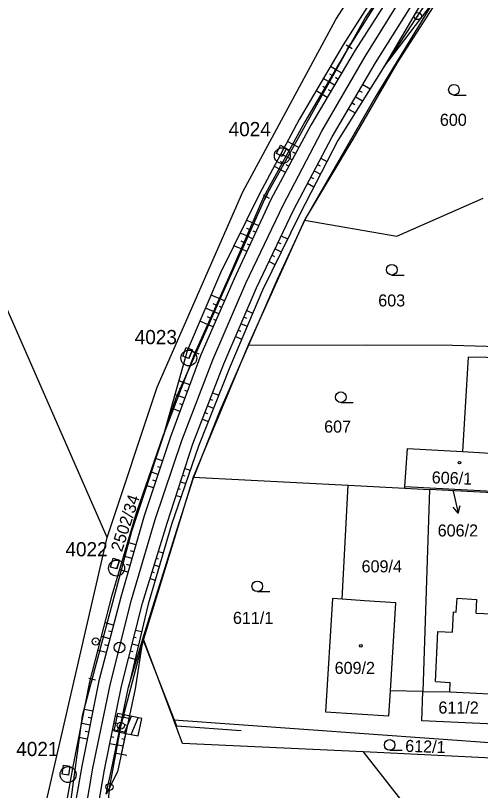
# Model space of a CAD drawing. Extents: x -558358 to -557517, y -1073786 to -1073189.
# Drawn here: x -558299.7 to -558234.1, y -1073668.8 to -1073559.5 of the extents above; entities that cross this region are included whole.
import ezdxf

# ---------------------------------------------------------------- set-up
doc = ezdxf.new("R2010")
doc.units = 0
for name, color, linetype in [('Body', 7, 'Continuous'), ('Hranice parcel', 7, 'Continuous'), ('Kolej', 7, 'Continuous'), ('Lomové body_krizky', 7, 'Continuous'), ('Návěst místo trati', 7, 'Continuous'), ('Parcelní čísla', 7, 'Continuous'), ('Plot - zábradlí', 7, 'Continuous'), ('Pop  PČ popisy', 7, 'Continuous'), ('Přejezd - štěrkové lože', 7, 'Continuous'), ('Sonda - šrafa - vrstevnice', 7, 'Continuous'), ('Svazek obcí údolí Desné', 7, 'Continuous'), ('Vnitřní kresba', 7, 'Continuous'), ('Vrstva 1', 7, 'Continuous'), ('Vrstva 60', 7, 'Continuous'), ('Značky budov', 7, 'Continuous'), ('Značky kultur', 7, 'Continuous'), ('ŽKN drážní hranice', 7, 'Continuous')]:
    doc.layers.add(name, color=color, linetype=linetype)

msp = doc.modelspace()

# ---------------------------------------------------------------- linework, layer by layer
at = {"layer": 'Body'}
for p, q in [((-558262.32, -1073577.78), (-558261.49, -1073578.24)), ((-558262.1, -1073579.36), (-558262.92, -1073578.93)), ((-558275.63, -1073606.33), (-558274.76, -1073606.67)), ((-558275.24, -1073607.87), (-558276.1, -1073607.53)), ((-558285.94, -1073636.03), (-558285.03, -1073636.3)), ((-558285.39, -1073637.54), (-558286.32, -1073637.3)), ((-558292.94, -1073665.22), (-558292.02, -1073665.39)), ((-558292.22, -1073666.67), (-558293.14, -1073666.49))]:
    msp.add_line(p, q, dxfattribs=at)
for points in [[(-558261.49, -1073578.24), (-558262.1, -1073579.36), (-558262.92, -1073578.93), (-558262.32, -1073577.78), (-558261.49, -1073578.24)], [(-558262.92, -1073578.93), (-558262.92, -1073578.93), (-558262.32, -1073577.78), (-558262.32, -1073577.78)], [(-558274.76, -1073606.67), (-558275.24, -1073607.87), (-558276.1, -1073607.53), (-558275.63, -1073606.33), (-558274.76, -1073606.67)], [(-558276.1, -1073607.53), (-558276.1, -1073607.53), (-558275.63, -1073606.33), (-558275.63, -1073606.33)], [(-558275.24, -1073607.87), (-558275.24, -1073607.87), (-558274.76, -1073606.67), (-558274.76, -1073606.67)], [(-558285.03, -1073636.3), (-558285.39, -1073637.54), (-558286.32, -1073637.3), (-558285.94, -1073636.03), (-558285.03, -1073636.3)], [(-558286.32, -1073637.3), (-558286.32, -1073637.3), (-558285.94, -1073636.03), (-558285.94, -1073636.03)], [(-558285.39, -1073637.54), (-558285.39, -1073637.54), (-558285.03, -1073636.3)], [(-558292.02, -1073665.39), (-558292.22, -1073666.67), (-558293.14, -1073666.49), (-558292.94, -1073665.22), (-558292.02, -1073665.39)], [(-558293.14, -1073666.49), (-558293.14, -1073666.49), (-558292.94, -1073665.22), (-558292.94, -1073665.22)]]:
    msp.add_lwpolyline(points, dxfattribs=at)
at = {"layer": 'Hranice parcel'}
for p, q in [((-558286.79, -1073633.11), (-558314.35, -1073570.26)), ((-558274.67, -1073624.61), (-558252.77, -1073625.76)), ((-558253.62, -1073641.82), (-558252.77, -1073625.76)), ((-558252.77, -1073625.76), (-558244.78, -1073626.18)), ((-558244.78, -1073626.18), (-558244.8, -1073625.91)), ((-558244.8, -1073625.91), (-558230.66, -1073626.67)), ((-558244.78, -1073626.18), (-558241.33, -1073626.36)), ((-558241.33, -1073626.36), (-558242.25, -1073654.84)), ((-558230.7, -1073626.92), (-558241.33, -1073626.36)), ((-558277.36, -1073658.89), (-558281.64, -1073647.46)), ((-558242.25, -1073654.84), (-558246.82, -1073654.76)), ((-558214.98, -1073663.38), (-558277.36, -1073658.89)), ((-558235.56, -1073682.51), (-558250.61, -1073663.38)), ((-558196.23, -1073665.95), (-558250.61, -1073663.38))]:
    msp.add_line(p, q, dxfattribs=at)
for points in [[(-558258.93, -1073588.36), (-558245.95, -1073590.61), (-558233.77, -1073585.24)], [(-558266.9, -1073605.97), (-558250.26, -1073605.94), (-558238.1, -1073605.99), (-558233.28, -1073606.15), (-558214.77, -1073606.72), (-558208.24, -1073606.85)], [(-558201.17, -1073622.6), (-558216.08, -1073622.11), (-558216.01, -1073620.62), (-558215.37, -1073608.44), (-558225.51, -1073607.88), (-558235.86, -1073607.68), (-558236.68, -1073621.01)], [(-558244.8, -1073625.91), (-558244.42, -1073620.56), (-558236.68, -1073621.01)], [(-558236.68, -1073621.01), (-558230.37, -1073621.38), (-558230.66, -1073626.67)], [(-558253.62, -1073641.82), (-558255.01, -1073641.72), (-558256, -1073657.72), (-558247.04, -1073658.27), (-558246.82, -1073654.76)], [(-558246.82, -1073654.76), (-558246.07, -1073642.32), (-558250.48, -1073642.05), (-558253.62, -1073641.82)], [(-558214.83, -1073660.26), (-558242.39, -1073658.97), (-558242.25, -1073654.84)], [(-558242.25, -1073654.84), (-558238.47, -1073654.91), (-558229.12, -1073655.37), (-558229.2, -1073656.96), (-558221.9, -1073657.32), (-558221.78, -1073654.92), (-558214.58, -1073655.27)], [(-558250.61, -1073663.38), (-558276.13, -1073662.17), (-558277.36, -1073658.89)]]:
    msp.add_lwpolyline(points, dxfattribs=at)
at = {"layer": 'Kolej'}
msp.add_lwpolyline([(-558287.37, -1073784.16), (-558289.56, -1073772.87), (-558290.66, -1073766.21), (-558291.24, -1073762.21), (-558292.77, -1073749.06), (-558293.62, -1073737.47), (-558294.02, -1073725.05), (-558293.93, -1073713.18), (-558293.34, -1073701.02), (-558292.27, -1073689.01), (-558290.77, -1073677.31), (-558288.8, -1073665.65), (-558286.32, -1073653.74), (-558283.34, -1073641.94), (-558280, -1073630.57), (-558276.23, -1073619.43), (-558271.87, -1073608.04), (-558267.23, -1073597.24), (-558261.98, -1073586.24), (-558256.49, -1073575.8), (-558250.41, -1073565.28), (-558246.06, -1073558.3)], dxfattribs=at)
at = {"layer": 'Lomové body_krizky'}
msp.add_line((-558247.8, -1073566.83), (-558237.59, -1073553.32), dxfattribs=at)
for points in [[(-558243.55, -1073526.52), (-558241.09, -1073532.31), (-558239.34, -1073536.46), (-558240.77, -1073539.1), (-558240.78, -1073543.51), (-558244.12, -1073548.8), (-558253.49, -1073563.6), (-558259.69, -1073574.14), (-558265.34, -1073584.72), (-558270.8, -1073595.81), (-558275.48, -1073606.81), (-558278.77, -1073618.5)], [(-558238.82, -1073534.05), (-558238.07, -1073536.86), (-558239.2, -1073538.21), (-558240, -1073543.71), (-558243.46, -1073549.18), (-558252.76, -1073564.02), (-558258.92, -1073574.47), (-558264.72, -1073585.09), (-558269.64, -1073596.42), (-558274.5, -1073607.3), (-558278.77, -1073618.5)], [(-558233.31, -1073548.35), (-558233.96, -1073547.13), (-558235.35, -1073547.54), (-558238.57, -1073552.68), (-558247.8, -1073566.83)], [(-558281.76, -1073647.44), (-558282.83, -1073654.48), (-558285.33, -1073666.2), (-558286.94, -1073669.34)], [(-558286.94, -1073669.34), (-558286.22, -1073666.1), (-558283.78, -1073654.25), (-558281.76, -1073647.44)]]:
    msp.add_lwpolyline(points, dxfattribs=at)
at = {"layer": 'Návěst místo trati'}
for p, q in [((-558243.02, -1073559.57), (-558242.92, -1073559.57)), ((-558243.02, -1073559.57), (-558242.92, -1073559.57)), ((-558253.08, -1073563.61), (-558252.23, -1073564.13)), ((-558252.91, -1073564.3), (-558252.4, -1073563.44)), ((-558264.8, -1073584.8), (-558263.91, -1073585.25)), ((-558264.58, -1073585.47), (-558264.13, -1073584.58)), ((-558274.76, -1073606.83), (-558273.84, -1073607.21)), ((-558274.49, -1073607.48), (-558274.11, -1073606.56)), ((-558288.45, -1073647.79), (-558288.35, -1073647.79)), ((-558288.45, -1073647.79), (-558288.35, -1073647.79)), ((-558288.78, -1073652.65), (-558289.01, -1073653.62)), ((-558288.41, -1073653.24), (-558289.38, -1073653.02)), ((-558285.36, -1073660.51), (-558284.35, -1073658.16)), ((-558283.38, -1073658.36), (-558284.38, -1073660.71)), ((-558283.4, -1073660.92), (-558282.4, -1073658.57)), ((-558285.48, -1073663.54), (-558284.01, -1073663.85))]:
    msp.add_line(p, q, dxfattribs=at)
msp.add_lwpolyline([(-558284.74, -1073663.7), (-558284.13, -1073660.76), (-558282.42, -1073661.12), (-558281.91, -1073658.67), (-558285.33, -1073657.96), (-558285.84, -1073660.4), (-558284.13, -1073660.76)], dxfattribs=at)
for centre, radius in [((-558242.97, -1073559.57), 0.5), ((-558242.97, -1073559.57), 0.5), ((-558288.4, -1073647.79), 0.5), ((-558288.4, -1073647.79), 0.5), ((-558285.03, -1073648.64), 0.75)]:
    msp.add_circle(centre, radius, dxfattribs=at)
at = {"layer": 'Plot - zábradlí'}
msp.add_lwpolyline([(-558267.89, -1073660.39), (-558276.96, -1073659.75), (-558281.76, -1073647.44), (-558277.17, -1073632.83), (-558274.66, -1073624.85), (-558270.86, -1073615.23), (-558262.75, -1073596.69), (-558258.8, -1073588.16), (-558252.1, -1073576.95), (-558245.86, -1073566.23), (-558237.59, -1073553.32), (-558234.22, -1073548.55), (-558231.78, -1073553.91)], dxfattribs=at)
at = {"layer": 'Pop  PČ popisy'}
for p, q in [((-558238.03, -1073626.44), (-558237.95, -1073626.78)), ((-558237.95, -1073626.78), (-558237.28, -1073629.7)), ((-558237.28, -1073629.7), (-558237.01, -1073628.62)), ((-558237.28, -1073629.7), (-558237.99, -1073628.84))]:
    msp.add_line(p, q, dxfattribs=at)
at = {"layer": 'Přejezd - štěrkové lože'}
for p, q in [((-558253.72, -1073567.59), (-558254.57, -1073567.09)), ((-558254.23, -1073568.45), (-558254.57, -1073568.25)), ((-558254.73, -1073569.31), (-558255.58, -1073568.81)), ((-558250.72, -1073569.23), (-558249.68, -1073569.83)), ((-558255.75, -1073571.03), (-558256.6, -1073570.53)), ((-558255.24, -1073570.18), (-558255.58, -1073569.97)), ((-558251.22, -1073570.09), (-558250.82, -1073570.32)), ((-558252.23, -1073571.81), (-558251.85, -1073572.04)), ((-558251.73, -1073570.95), (-558250.75, -1073571.53)), ((-558252.74, -1073572.68), (-558251.81, -1073573.22)), ((-558259.75, -1073578.09), (-558260.64, -1073577.62)), ((-558260.7, -1073579.86), (-558261.6, -1073579.37)), ((-558260.23, -1073578.97), (-558260.58, -1073578.78)), ((-558261.17, -1073580.74), (-558261.53, -1073580.54)), ((-558257.11, -1073580.51), (-558256.76, -1073580.7)), ((-558256.64, -1073579.63), (-558255.78, -1073580.08)), ((-558261.64, -1073581.62), (-558262.56, -1073581.13)), ((-558257.58, -1073581.4), (-558256.7, -1073581.86)), ((-558258.04, -1073582.28), (-558257.69, -1073582.47)), ((-558258.51, -1073583.16), (-558257.62, -1073583.64)), ((-558265.41, -1073589.15), (-558266.31, -1073588.74)), ((-558265.83, -1073590.06), (-558266.18, -1073589.9)), ((-558266.26, -1073590.97), (-558267.1, -1073590.57)), ((-558262.66, -1073591.49), (-558262.31, -1073591.66)), ((-558262.23, -1073590.59), (-558261.34, -1073591.01)), ((-558267.1, -1073592.78), (-558267.9, -1073592.41)), ((-558266.68, -1073591.87), (-558267.01, -1073591.72)), ((-558263.09, -1073592.4), (-558262.22, -1073592.81)), ((-558263.52, -1073593.3), (-558263.18, -1073593.46)), ((-558263.95, -1073594.21), (-558263.11, -1073594.6)), ((-558270.25, -1073599.75), (-558270.98, -1073599.43)), ((-558271.04, -1073601.58), (-558271.8, -1073601.26)), ((-558270.65, -1073600.67), (-558270.94, -1073600.54)), ((-558267.08, -1073601.12), (-558266.26, -1073601.47)), ((-558271.44, -1073602.5), (-558271.75, -1073602.37)), ((-558267.48, -1073602.04), (-558267.14, -1073602.18)), ((-558271.84, -1073603.42), (-558272.62, -1073603.08)), ((-558267.87, -1073602.96), (-558267.03, -1073603.32)), ((-558268.27, -1073603.87), (-558267.93, -1073604.02)), ((-558268.66, -1073604.79), (-558267.81, -1073605.16)), ((-558275.12, -1073611.58), (-558276.01, -1073611.26)), ((-558275.82, -1073613.46), (-558276.72, -1073613.12)), ((-558275.47, -1073612.52), (-558275.83, -1073612.39)), ((-558271.9, -1073612.7), (-558271.03, -1073613.04)), ((-558276.16, -1073614.4), (-558276.53, -1073614.26)), ((-558272.26, -1073613.63), (-558271.92, -1073613.77)), ((-558276.51, -1073615.33), (-558277.43, -1073614.99)), ((-558272.99, -1073615.5), (-558272.65, -1073615.63)), ((-558272.63, -1073614.57), (-558271.77, -1073614.9)), ((-558273.35, -1073616.43), (-558272.5, -1073616.76)), ((-558278.98, -1073622.32), (-558279.97, -1073621.99)), ((-558279.29, -1073623.27), (-558279.69, -1073623.14)), ((-558279.61, -1073624.22), (-558280.62, -1073623.88)), ((-558276.13, -1073624.32), (-558275.83, -1073624.42)), ((-558275.82, -1073623.37), (-558275.05, -1073623.62)), ((-558279.93, -1073625.17), (-558280.33, -1073625.03)), ((-558276.44, -1073625.28), (-558275.7, -1073625.51)), ((-558280.24, -1073626.12), (-558281.28, -1073625.77)), ((-558276.74, -1073626.23), (-558276.46, -1073626.32)), ((-558277.05, -1073627.18), (-558276.35, -1073627.4)), ((-558282.74, -1073634.18), (-558283.87, -1073633.85)), ((-558283.02, -1073635.14), (-558283.47, -1073635.01)), ((-558279.54, -1073635.08), (-558278.88, -1073635.29)), ((-558283.3, -1073636.1), (-558284.44, -1073635.77)), ((-558279.84, -1073636.04), (-558279.57, -1073636.12)), ((-558283.57, -1073637.06), (-558284.03, -1073636.93)), ((-558280.13, -1073637), (-558279.44, -1073637.21)), ((-558283.85, -1073638.02), (-558285.01, -1073637.69)), ((-558280.43, -1073637.95), (-558280.15, -1073638.04)), ((-558280.72, -1073638.91), (-558280.01, -1073639.13)), ((-558285.89, -1073645.48), (-558287.07, -1073645.18)), ((-558282.76, -1073646.19), (-558281.92, -1073646.4)), ((-558286.39, -1073647.42), (-558287.57, -1073647.11)), ((-558286.14, -1073646.45), (-558286.61, -1073646.33)), ((-558283.01, -1073647.16), (-558282.67, -1073647.25)), ((-558286.64, -1073648.39), (-558287.11, -1073648.26)), ((-558283.25, -1073648.13), (-558282.38, -1073648.35)), ((-558286.89, -1073649.35), (-558288.06, -1073649.05)), ((-558283.5, -1073649.1), (-558283.14, -1073649.19)), ((-558283.74, -1073650.07), (-558282.84, -1073650.3)), ((-558288.8, -1073657.64), (-558289.98, -1073657.4)), ((-558285.61, -1073658.27), (-558284.65, -1073658.46)), ((-558289.19, -1073659.6), (-558290.37, -1073659.36)), ((-558288.99, -1073658.62), (-558289.47, -1073658.52)), ((-558285.81, -1073659.25), (-558285.43, -1073659.32)), ((-558289.39, -1073660.58), (-558289.86, -1073660.48)), ((-558286.01, -1073660.23), (-558285.05, -1073660.42)), ((-558289.59, -1073661.56), (-558290.77, -1073661.32)), ((-558286.21, -1073661.21), (-558285.82, -1073661.28)), ((-558286.41, -1073662.19), (-558285.45, -1073662.38))]:
    msp.add_line(p, q, dxfattribs=at)
for points in [[(-558236.57, -1073541.18), (-558242.63, -1073550.03), (-558251.8, -1073564.36), (-558258.08, -1073574.96), (-558263.68, -1073585.42), (-558268.89, -1073596.63), (-558273.56, -1073607.36), (-558277.84, -1073618.92), (-558281.55, -1073630.05), (-558284.86, -1073641.54), (-558287.93, -1073653.35), (-558290.36, -1073665.39), (-558292.44, -1073677.06), (-558293.84, -1073688.83), (-558294.98, -1073700.92), (-558295.5, -1073713.2), (-558295.65, -1073725.09), (-558295.34, -1073737.57), (-558294.51, -1073749.18), (-558292.85, -1073761.97)], [(-558289.76, -1073760.35), (-558291.17, -1073748.87), (-558292.01, -1073737.3), (-558292.42, -1073725.02), (-558292.29, -1073713.18), (-558291.76, -1073701.11), (-558290.62, -1073689.2), (-558289.11, -1073677.44), (-558287.17, -1073665.92), (-558284.76, -1073654.08), (-558281.79, -1073642.38), (-558278.31, -1073631.08), (-558274.71, -1073619.92), (-558270.32, -1073608.64), (-558265.7, -1073597.9), (-558260.51, -1073586.94), (-558255.05, -1073576.61), (-558248.93, -1073566.18), (-558239.9, -1073551.79), (-558235.83, -1073545.74)], [(-558235.83, -1073545.74), (-558235.98, -1073547.31), (-558239.26, -1073552.18), (-558247.8, -1073566.83), (-558254.24, -1073577.1), (-558259.62, -1073587.52), (-558264.88, -1073598.21), (-558269.46, -1073609.08), (-558273.88, -1073620.25), (-558277.7, -1073631.3), (-558281, -1073642.51), (-558283.78, -1073654.25)], [(-558296.59, -1073713.22), (-558296.03, -1073701.28), (-558294.7, -1073688.81), (-558293.68, -1073677.15), (-558291.54, -1073665.18), (-558289.2, -1073653.49), (-558286.07, -1073641.28), (-558282.62, -1073629.65), (-558278.77, -1073618.5)]]:
    msp.add_lwpolyline(points, dxfattribs=at)
at = {"layer": 'Sonda - šrafa - vrstevnice'}
for p, q in [((-558254.57, -1073567.09), (-558255.29, -1073566.66)), ((-558255.58, -1073568.81), (-558256.31, -1073568.38)), ((-558255.07, -1073567.95), (-558255.36, -1073567.78)), ((-558256.09, -1073569.67), (-558256.38, -1073569.5)), ((-558256.6, -1073570.53), (-558257.32, -1073570.11)), ((-558260.64, -1073577.62), (-558261.35, -1073577.24)), ((-558261.12, -1073578.5), (-558261.4, -1073578.35)), ((-558261.6, -1073579.38), (-558262.29, -1073579)), ((-558262.08, -1073580.25), (-558262.35, -1073580.1)), ((-558262.56, -1073581.13), (-558263.23, -1073580.76)), ((-558266.31, -1073588.74), (-558267.15, -1073588.38)), ((-558267.1, -1073590.58), (-558268.03, -1073590.17)), ((-558266.7, -1073589.66), (-558267.06, -1073589.51)), ((-558267.5, -1073591.49), (-558267.89, -1073591.32)), ((-558267.9, -1073592.41), (-558268.92, -1073591.97)), ((-558270.98, -1073599.43), (-558272.13, -1073598.92)), ((-558271.39, -1073600.35), (-558271.84, -1073600.15)), ((-558271.8, -1073601.26), (-558272.91, -1073600.76)), ((-558272.21, -1073602.17), (-558272.65, -1073601.98)), ((-558272.62, -1073603.09), (-558273.7, -1073602.6)), ((-558276.01, -1073611.27), (-558276.67, -1073611.02)), ((-558276.37, -1073612.2), (-558276.59, -1073612.11)), ((-558276.72, -1073613.14), (-558277.21, -1073612.95)), ((-558277.08, -1073614.07), (-558277.24, -1073614.01)), ((-558277.44, -1073615.01), (-558277.75, -1073614.89)), ((-558283.73, -1073658.67), (-558284.65, -1073658.48)), ((-558284.14, -1073660.63), (-558285.05, -1073660.44)), ((-558283.94, -1073659.65), (-558284.3, -1073659.57)), ((-558284.35, -1073661.61), (-558284.71, -1073661.53)), ((-558284.56, -1073662.58), (-558285.45, -1073662.39))]:
    msp.add_line(p, q, dxfattribs=at)
at = {"layer": 'Svazek obcí údolí Desné'}
for p, q in [((-558258.93, -1073588.36), (-558266.9, -1073605.97)), ((-558266.9, -1073605.97), (-558274.67, -1073624.61)), ((-558274.67, -1073624.61), (-558281.64, -1073647.46))]:
    msp.add_line(p, q, dxfattribs=at)
for points in [[(-558286.79, -1073633.11), (-558279.73, -1073611.9), (-558267.63, -1073584.34), (-558254.51, -1073560.06), (-558239.03, -1073535.96)], [(-558237.23, -1073540.41), (-558250.35, -1073559.71), (-558264.4, -1073584.99), (-558277.08, -1073613.49), (-558283.33, -1073632.3), (-558290.3, -1073658.29), (-558296.01, -1073700.28), (-558297.13, -1073716.84), (-558297.21, -1073758.56)], [(-558233.76, -1073548.97), (-558235.85, -1073550.36), (-558241.19, -1073558.21), (-558248.9, -1073570.88), (-558258.93, -1073588.36)], [(-558299.09, -1073706.57), (-558299.03, -1073702.13), (-558295.75, -1073672.1), (-558286.79, -1073633.11)], [(-558281.64, -1073647.46), (-558284.84, -1073659.61), (-558286.44, -1073668.26), (-558287.25, -1073676.53)]]:
    msp.add_lwpolyline(points, dxfattribs=at)
at = {"layer": 'Vnitřní kresba'}
for p, q in [((-558237.54, -1073643.65), (-558237.44, -1073641.68)), ((-558237.44, -1073641.68), (-558234.63, -1073641.89)), ((-558234.73, -1073643.79), (-558234.63, -1073641.89)), ((-558238.06, -1073646.47), (-558237.92, -1073643.63)), ((-558237.92, -1073643.63), (-558237.54, -1073643.65)), ((-558234.73, -1073643.79), (-558228.55, -1073644.09)), ((-558240.5, -1073653.46), (-558240.16, -1073646.37)), ((-558240.16, -1073646.37), (-558238.06, -1073646.47)), ((-558240.5, -1073653.46), (-558238.41, -1073653.56)), ((-558238.47, -1073654.91), (-558238.41, -1073653.56))]:
    msp.add_line(p, q, dxfattribs=at)
at = {"layer": 'Vrstva 60'}
for p, q in [((-558262.08, -1073579.26), (-558262.08, -1073579.26)), ((-558262.08, -1073579.26), (-558262.08, -1073579.26)), ((-558275.26, -1073607.8), (-558275.26, -1073607.8)), ((-558275.26, -1073607.8), (-558275.26, -1073607.8)), ((-558285.45, -1073637.44), (-558285.45, -1073637.44)), ((-558285.45, -1073637.44), (-558285.45, -1073637.44)), ((-558292.29, -1073666.57), (-558292.29, -1073666.57)), ((-558292.29, -1073666.57), (-558292.29, -1073666.57))]:
    msp.add_line(p, q, dxfattribs=at)
for centre, radius in [((-558262.08, -1073579.26), 1.12), ((-558262.08, -1073579.26), 1.12), ((-558262.08, -1073579.26), 0.045), ((-558262.08, -1073579.26), 0.045), ((-558275.26, -1073607.8), 1.12), ((-558275.26, -1073607.8), 1.12), ((-558275.26, -1073607.8), 0.045), ((-558275.26, -1073607.8), 0.045), ((-558285.45, -1073637.44), 1.12), ((-558285.45, -1073637.44), 1.12), ((-558285.45, -1073637.44), 0.045), ((-558285.45, -1073637.44), 0.045), ((-558292.29, -1073666.57), 1.12), ((-558292.29, -1073666.57), 0.045)]:
    msp.add_circle(centre, radius, dxfattribs=at)
at = {"layer": 'Značky budov'}
for centre in [(-558237.09, -1073622.57), (-558251.01, -1073648.41)]:
    msp.add_circle(centre, 0.175, dxfattribs=at)
at = {"layer": 'Značky kultur'}
for p, q in [((-558237.88, -1073570.71), (-558236.13, -1073570.71)), ((-558246.64, -1073596.1), (-558244.89, -1073596.1)), ((-558253.83, -1073614.07), (-558252.08, -1073614.07)), ((-558265.61, -1073640.76), (-558263.86, -1073640.76)), ((-558246.94, -1073663.14), (-558245.19, -1073663.14))]:
    msp.add_line(p, q, dxfattribs=at)
for centre in [(-558237.88, -1073569.96), (-558246.64, -1073595.35), (-558253.83, -1073613.32), (-558265.61, -1073640.01), (-558246.94, -1073662.39)]:
    msp.add_circle(centre, 0.75, dxfattribs=at)
at = {"layer": 'ŽKN drážní hranice'}
for p, q in [((-558284.9, -1073659.66), (-558284.8, -1073659.66)), ((-558286.5, -1073668.31), (-558286.4, -1073668.31))]:
    msp.add_line(p, q, dxfattribs=at)
for centre in [(-558284.85, -1073659.66), (-558286.45, -1073668.31)]:
    msp.add_circle(centre, 0.499, dxfattribs=at)

# ---------------------------------------------------------------- texts
at = {"layer": 'Parcelní čísla'}
for s, p in [('600', (-558239.86, -1073575.05)), ('603', (-558248.55, -1073600.53)), ('607', (-558256.18, -1073618.33)), ('606/2', (-558240.17, -1073632.98)), ('609/4', (-558250.9, -1073638.04)), ('611/1', (-558269.04, -1073645.31)), ('609/2', (-558254.7, -1073652.37)), ('611/2', (-558240.07, -1073657.96))]:
    msp.add_text(s, height=1.7, dxfattribs=at).set_placement(p)
for s, p in [('606/1', (-558241.03, -1073625.48)), ('612/1', (-558244.77, -1073663.35))]:
    msp.add_text(s, height=1.7, rotation=358, dxfattribs=at).set_placement(p)
at = {"layer": 'Vrstva 1'}
msp.add_text('2502/34', height=1.7, rotation=72, dxfattribs=at).set_placement((-558284.7, -1073635.25))
at = {"layer": 'Vrstva 60'}
for s, p in [('4024', (-558269.65, -1073576.51)), ('4023', (-558282.89, -1073605.85)), ('4022', (-558292.66, -1073635.78)), ('4021', (-558299.6, -1073663.96))]:
    msp.add_text(s, height=2, dxfattribs=at).set_placement(p)

doc.saveas('drawing.dxf')
